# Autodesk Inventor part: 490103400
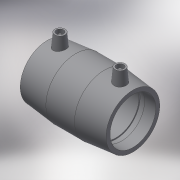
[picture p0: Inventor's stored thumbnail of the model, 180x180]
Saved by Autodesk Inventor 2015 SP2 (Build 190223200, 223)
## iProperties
Created: 2017-06
Part Number: 490103400
Material: Generic
Description: PLASSON COUPLER 400-400
Document SubType Name: Modeling
Designer: KIM
Mass: 14324.8 g
Surface Area: 9359.62 cm^2
Volume: 14324.8 cm^3
Density: 1 g/cm^3
Appearance: Default
Author: KIM
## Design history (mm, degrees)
derived "490104.ipt"
feature "Solid1::490104.ipt"
tag "TaggingFeature1"
body "Solid1"
other parameters: "d0" = 293, "d2" = 485, "d3" = 145, "d4" = 97.66667, "d5" = 436.5, "d8" = 168 deg, "d10" = 58, "d11" = 19.33333, "d13" = 293, "d14" = 17.6296, "d15" = 145, "d16" = 145, "d19" = 3.52592, "d20" = 168 deg, "d22" = 455.9, "d23" = 485, "d24" = 442.223, "d25" = 135 deg, "d26" = 161.15, "d27" = 135 deg, "d29" = 231, "d30" = 14, "d31" = 102.55, "d34" = 5 deg, "d35" = 15, "d39" = 5 deg, "d41" = 4, "d42" = 14, "d43" = 0, "d45" = 4, "d46" = 14, "d47" = 0, "d48" = 3, "d49" = 0, "d50" = 3, "d51" = 0, "d52" = 42.05, "d53" = 10.5125, "L_" = 293, "L_1" = 145, "D_" = 485, "A_" = 231, "d_2" = 12
